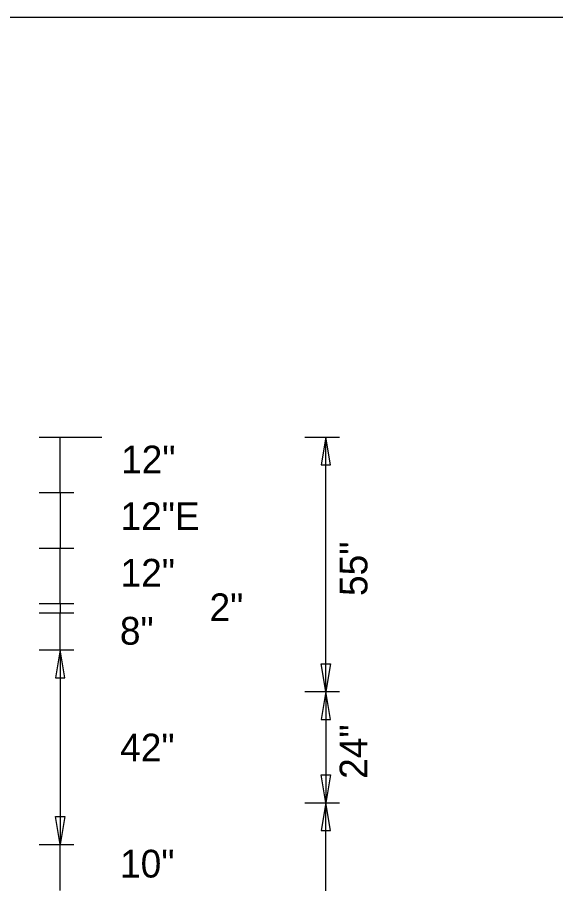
# Model space of a CAD drawing. Extents: x 119523 to 121850, y -23542 to -19972.
# Drawn here: x 121457.7 to 121574, y -22914.3 to -22727.2 of the extents above; entities that cross this region are included whole.
import ezdxf

# ---------------------------------------------------------------- set-up
doc = ezdxf.new("R2010")
doc.units = 0
doc.layers.add('GSDims', color=7, linetype='Continuous')
doc.layers.add('SheetLinesMisc2_dp', color=7, linetype='Continuous')

msp = doc.modelspace()

# ---------------------------------------------------------------- linework, layer by layer
at = {"layer": 'GSDims'}
for p, q in [((121462.4, -22817.83), (121469.9, -22817.83)), ((121462.4, -22817.83), (121475.94, -22817.83)), ((121466.9, -22829.83), (121466.9, -22817.83)), ((121519.81, -22817.83), (121527.31, -22817.83)), ((121524.31, -22872.83), (121524.31, -22817.83)), ((121462.4, -22829.83), (121469.9, -22829.83)), ((121462.4, -22829.83), (121469.9, -22829.83)), ((121466.9, -22829.83), (121466.9, -22841.83)), ((121462.4, -22841.83), (121469.9, -22841.83)), ((121462.4, -22841.83), (121469.9, -22841.83)), ((121466.9, -22853.83), (121466.9, -22841.83)), ((121462.4, -22853.83), (121469.9, -22853.83)), ((121462.4, -22853.83), (121469.9, -22853.83)), ((121466.9, -22853.83), (121466.9, -22855.83)), ((121462.4, -22855.83), (121469.9, -22855.83)), ((121462.4, -22855.83), (121469.9, -22855.83)), ((121466.9, -22863.83), (121466.9, -22855.83)), ((121462.4, -22863.83), (121469.9, -22863.83)), ((121462.4, -22863.83), (121469.9, -22863.83)), ((121466.9, -22863.83), (121466.9, -22905.83)), ((121519.81, -22872.83), (121527.31, -22872.83)), ((121519.81, -22872.83), (121527.31, -22872.83)), ((121524.31, -22872.83), (121524.31, -22896.83)), ((121519.81, -22896.83), (121527.31, -22896.83)), ((121519.81, -22896.83), (121527.31, -22896.83)), ((121524.31, -22967.83), (121524.31, -22896.83)), ((121462.4, -22905.83), (121469.9, -22905.83)), ((121462.4, -22905.83), (121469.9, -22905.83)), ((121466.9, -22915.83), (121466.9, -22905.83))]:
    msp.add_line(p, q, dxfattribs=at)
for points in [[(121524.31, -22817.83), (121523.31, -22823.83), (121525.31, -22823.83)], [(121466.9, -22863.83), (121465.9, -22869.83), (121467.9, -22869.83)], [(121524.31, -22872.83), (121523.31, -22866.83), (121525.31, -22866.83)], [(121524.31, -22872.83), (121523.31, -22878.83), (121525.31, -22878.83)], [(121524.31, -22896.83), (121523.31, -22890.83), (121525.31, -22890.83)], [(121524.31, -22896.83), (121523.31, -22902.83), (121525.31, -22902.83)], [(121466.9, -22905.83), (121465.9, -22899.83), (121467.9, -22899.83)]]:
    msp.add_lwpolyline(points, close=True, dxfattribs=at)
at = {"layer": 'SheetLinesMisc2_dp'}
msp.add_line((121023.51, -22727.16), (121760.29, -22727.16), dxfattribs=at)

# ---------------------------------------------------------------- texts
at = {"layer": 'GSDims'}
for s, p in [('12"', (121480.07, -22825.69)), ('12"E', (121479.94, -22837.94)), ('12"', (121479.96, -22850.16)), ('2"', (121499.19, -22857.61)), ('8"', (121479.82, -22862.69)), ('42"', (121479.88, -22887.92)), ('10"', (121479.85, -22913))]:
    msp.add_text(s, height=6, dxfattribs=at).set_placement(p)
for s, p in [('55"', (121533.31, -22852.19)), ('24"', (121533.31, -22891.69))]:
    msp.add_text(s, height=6, rotation=90, dxfattribs=at).set_placement(p)

doc.saveas('drawing.dxf')
